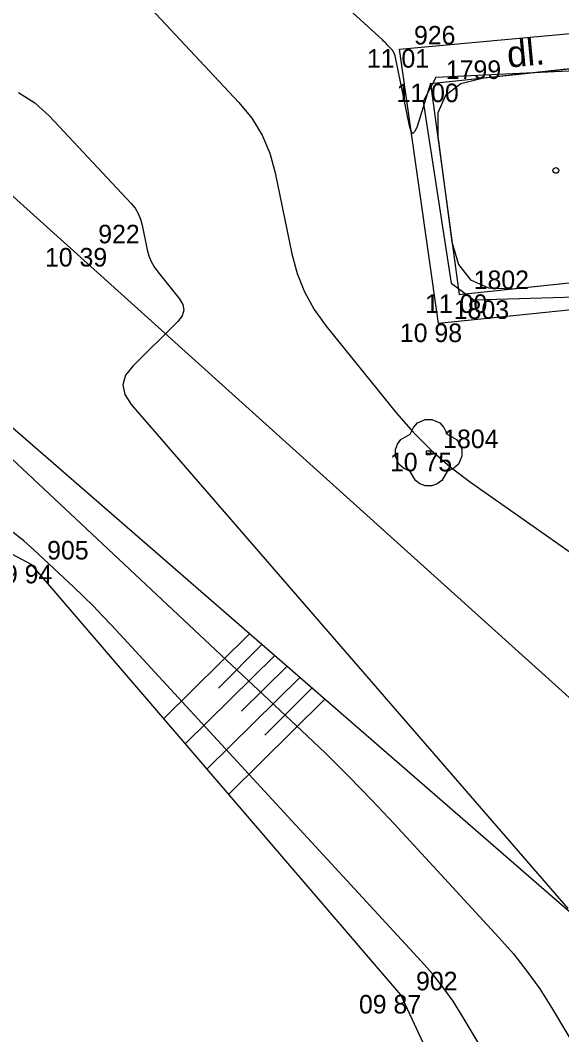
# Model space of a CAD drawing. Extents: x -711234 to -710007, y -1026313 to -1025448.
# Drawn here: x -710926.22 to -710918.05, y -1025891.41 to -1025876.1 of the extents above; entities that cross this region are included whole.
import ezdxf

# ---------------------------------------------------------------- set-up
doc = ezdxf.new("R2010")
doc.units = 0
for name, color, linetype in [('Ex_Major Contours', 7, 'Continuous'), ('Ex_Minor Contours', 7, 'Continuous'), ('Z_body', 7, 'Continuous'), ('Z_body_cisla', 7, 'Continuous'), ('Z_body_vysky_redukovane', 7, 'Continuous'), ('Z_budova', 7, 'Continuous'), ('Z_hrany_paty', 7, 'Continuous'), ('Z_katastr_hranice', 7, 'Continuous'), ('Z_katastr_znacky_budov', 7, 'Continuous'), ('Z_pole_rozhranni', 7, 'Continuous'), ('Z_popisy', 7, 'Continuous'), ('Z_rozhranni', 7, 'Continuous'), ('Z_technicke_srafy', 7, 'Continuous'), ('Z_zelen_jednotliva', 7, 'Continuous')]:
    doc.layers.add(name, color=color, linetype=linetype)

# ---------------------------------------------------------------- blocks, each defined once
blk = doc.blocks.new('POINT_DISPLAY')
blk.add_line((0, 0), (0, 0))
blk = doc.blocks.new('Z24')
for p, q in [((-0.17, 0.45), (-0.05, 0.5)), ((-0.05, 0.5), (0.05, 0.5)), ((0.05, 0.5), (0.17, 0.45)), ((-0.28, 0.28), (-0.23, 0.38)), ((-0.23, 0.38), (-0.17, 0.45)), ((0.17, 0.45), (0.23, 0.38)), ((0.23, 0.38), (0.28, 0.28)), ((-0.47, 0.13), (-0.42, 0.2)), ((-0.42, 0.2), (-0.28, 0.28)), ((0.28, 0.28), (0.42, 0.2)), ((0.42, 0.2), (0.47, 0.13)), ((-0.5, 0.05), (-0.47, 0.13)), ((-0.5, -0.05), (-0.5, 0.05)), ((-0.03, -0.03), (-0.03, 0.03)), ((-0.03, 0.03), (0.03, 0.03)), ((0.03, 0.03), (0.03, -0.03)), ((0.47, 0.13), (0.5, 0.05)), ((0.5, 0.05), (0.5, -0.05)), ((-0.45, -0.17), (-0.5, -0.05)), ((0.03, -0.03), (-0.03, -0.03)), ((0.5, -0.05), (0.45, -0.17)), ((-0.38, -0.23), (-0.45, -0.17)), ((-0.28, -0.28), (-0.38, -0.23)), ((-0.2, -0.42), (-0.28, -0.28)), ((0.28, -0.28), (0.2, -0.42)), ((0.38, -0.23), (0.28, -0.28)), ((0.45, -0.17), (0.38, -0.23)), ((-0.13, -0.47), (-0.2, -0.42)), ((0.2, -0.42), (0.13, -0.47)), ((-0.05, -0.5), (-0.13, -0.47)), ((0.05, -0.5), (-0.05, -0.5)), ((0.13, -0.47), (0.05, -0.5))]:
    blk.add_line(p, q)

msp = doc.modelspace()

# ---------------------------------------------------------------- linework, layer by layer
at = {"layer": 'Ex_Major Contours'}
for points in [[(-710920.03, -1025877.06), (-710920.235, -1025877.705), (-710920.268, -1025877.785), (-710920.298, -1025877.811), (-710920.325, -1025877.782), (-710920.349, -1025877.699), (-710920.566, -1025876.639), (-710920.573, -1025876.615), (-710920.583, -1025876.592), (-710920.596, -1025876.57), (-710920.612, -1025876.55), (-710920.683, -1025876.474), (-710920.701, -1025876.456), (-710920.72, -1025876.437), (-710920.738, -1025876.419), (-710920.757, -1025876.401), (-710923.985, -1025873.453)], [(-710919.02, -1025892.014), (-710919.553, -1025891.125), (-710919.692, -1025890.906), (-710919.841, -1025890.696), (-710920.001, -1025890.493), (-710920.171, -1025890.299), (-710924.835, -1025885.238), (-710924.975, -1025885.088), (-710925.118, -1025884.941), (-710925.264, -1025884.797), (-710925.412, -1025884.655), (-710926.011, -1025884.094), (-710926.164, -1025883.958), (-710926.324, -1025883.831)]]:
    msp.add_lwpolyline(points, dxfattribs=at)
msp.add_lwpolyline([(-710916.555, -1025879.868), (-710916.326, -1025879.692), (-710916.21, -1025879.428), (-710916.208, -1025879.075), (-710916.422, -1025877.485), (-710916.519, -1025877.142), (-710916.703, -1025876.91), (-710916.972, -1025876.787), (-710917.328, -1025876.774), (-710919.232, -1025876.976), (-710919.575, -1025877.062), (-710919.804, -1025877.238), (-710919.92, -1025877.502), (-710919.922, -1025877.855), (-710919.708, -1025879.445), (-710919.611, -1025879.788), (-710919.427, -1025880.02), (-710919.158, -1025880.143), (-710918.802, -1025880.156), (-710916.898, -1025879.954)], close=True, dxfattribs=at)
at = {"layer": 'Ex_Minor Contours'}
for points in [[(-710926.01, -1025874.036), (-710922.921, -1025877.343), (-710922.727, -1025877.58), (-710922.571, -1025877.837), (-710922.452, -1025878.112), (-710922.371, -1025878.407), (-710922.121, -1025879.626), (-710922.042, -1025879.923), (-710921.929, -1025880.204), (-710921.783, -1025880.47), (-710921.605, -1025880.719), (-710920.544, -1025882.031), (-710920.293, -1025882.321), (-710920.024, -1025882.591), (-710919.736, -1025882.842), (-710919.43, -1025883.073), (-710917.066, -1025884.735)], [(-710926.24, -1025877.192), (-710925.996, -1025877.35), (-710925.775, -1025877.552), (-710924.545, -1025878.869), (-710924.486, -1025878.941), (-710924.438, -1025879.02), (-710924.402, -1025879.104), (-710924.377, -1025879.194), (-710924.301, -1025879.566), (-710924.277, -1025879.657), (-710924.242, -1025879.743), (-710924.198, -1025879.824), (-710924.143, -1025879.9), (-710923.819, -1025880.301), (-710923.765, -1025880.392), (-710923.75, -1025880.48), (-710923.775, -1025880.566), (-710923.839, -1025880.649), (-710924.521, -1025881.321), (-710924.628, -1025881.461), (-710924.668, -1025881.605), (-710924.64, -1025881.751), (-710924.544, -1025881.9), (-710917.959, -1025889.505)], [(-710927.163, -1025881.956), (-710921.975, -1025886.821), (-710921.615, -1025887.164), (-710921.261, -1025887.514), (-710920.915, -1025887.871), (-710920.574, -1025888.234), (-710919.001, -1025889.941), (-710918.782, -1025890.191), (-710918.577, -1025890.45), (-710918.386, -1025890.72), (-710918.209, -1025891), (-710917.326, -1025892.472)]]:
    msp.add_lwpolyline(points, dxfattribs=at)
at = {"layer": 'Z_budova'}
for p, q in [((-710920.03, -1025877.06), (-710916.53, -1025876.69)), ((-710920.03, -1025877.06), (-710919.6, -1025880.24)), ((-710919.6, -1025880.24), (-710916.1, -1025879.87))]:
    msp.add_line(p, q, dxfattribs=at)
at = {"layer": 'Z_hrany_paty'}
msp.add_line((-710927.84, -1025880.94), (-710917.23, -1025890.17), dxfattribs=at)
at = {"layer": 'Z_katastr_hranice'}
for points in [[(-710919.95, -1025876.97), (-710920.14, -1025877.33), (-710919.72, -1025880.07), (-710919.38, -1025880.32), (-710916.3, -1025880.23), (-710916.23, -1025879.8), (-710916.59, -1025877.07), (-710916.9, -1025876.82), (-710919.95, -1025876.97)], [(-710916.27, -1025887.83), (-710926.53, -1025878.58), (-710938.23, -1025878.26)]]:
    msp.add_lwpolyline(points, dxfattribs=at)
at = {"layer": 'Z_katastr_znacky_budov'}
msp.add_circle((-710918.142, -1025878.37), 0.0437, dxfattribs=at)
at = {"layer": 'Z_pole_rozhranni'}
for p, q in [((-710926.04, -1025884.32), (-710932.36, -1025880.98)), ((-710920.48, -1025890.81), (-710926.04, -1025884.32)), ((-710918.15, -1025895.76), (-710920.48, -1025890.81))]:
    msp.add_line(p, q, dxfattribs=at)
at = {"layer": 'Z_rozhranni'}
for p, q in [((-710920.5, -1025876.54), (-710916.17, -1025876.14)), ((-710919.91, -1025880.68), (-710920.5, -1025876.54)), ((-710915.58, -1025880.23), (-710919.91, -1025880.68))]:
    msp.add_line(p, q, dxfattribs=at)
at = {"layer": 'Z_technicke_srafy'}
for p, q in [((-710922.76, -1025885.36), (-710924.05, -1025886.64)), ((-710922.57, -1025885.52), (-710923.23, -1025886.18)), ((-710922.38, -1025885.69), (-710923.73, -1025887.02)), ((-710922.19, -1025885.85), (-710922.88, -1025886.53)), ((-710922, -1025886.02), (-710923.4, -1025887.4)), ((-710921.82, -1025886.18), (-710922.53, -1025886.89)), ((-710921.63, -1025886.35), (-710923.07, -1025887.78))]:
    msp.add_line(p, q, dxfattribs=at)

# ---------------------------------------------------------------- block references
at = {"layer": 'Z_body'}
for p in [(-710920.5, -1025876.54), (-710920.03, -1025877.06), (-710925.26, -1025879.54), (-710919.6, -1025880.24), (-710919.91, -1025880.68), (-710920.06, -1025882.63), (-710926.04, -1025884.32), (-710920.48, -1025890.81)]:
    msp.add_blockref('POINT_DISPLAY', p, dxfattribs=at)
at = {"layer": 'Z_zelen_jednotliva'}
msp.add_blockref('Z24', (-710920.06, -1025882.63), dxfattribs=at)

# ---------------------------------------------------------------- texts
at = {"layer": 'Z_body_cisla'}
for s, p in [('926', (-710920.28, -1025876.47)), ('1799', (-710919.8, -1025876.99)), ('922', (-710925.04, -1025879.47)), ('1802', (-710919.38, -1025880.16)), ('1803', (-710919.68, -1025880.61)), ('1804', (-710919.84, -1025882.56)), ('905', (-710925.81, -1025884.24)), ('902', (-710920.25, -1025890.74))]:
    msp.add_text(s, height=0.28, dxfattribs=at).set_placement(p)
at = {"layer": 'Z_body_vysky_redukovane'}
for s, p in [('11 01', (-710920.99, -1025876.82)), ('11 00', (-710920.543, -1025877.34)), ('10 39', (-710925.843, -1025879.82)), ('11 00', (-710920.113, -1025880.52)), ('10 98', (-710920.493, -1025880.96)), ('10 75', (-710920.643, -1025882.91)), ('09 94', (-710926.67, -1025884.6)), ('09 87', (-710921.11, -1025891.09))]:
    msp.add_text(s, height=0.28, dxfattribs=at).set_placement(p)
at = {"layer": 'Z_popisy'}
msp.add_text('dl.', height=0.4, rotation=5.4, dxfattribs=at).set_placement((-710918.86, -1025876.82))

doc.saveas('drawing.dxf')
